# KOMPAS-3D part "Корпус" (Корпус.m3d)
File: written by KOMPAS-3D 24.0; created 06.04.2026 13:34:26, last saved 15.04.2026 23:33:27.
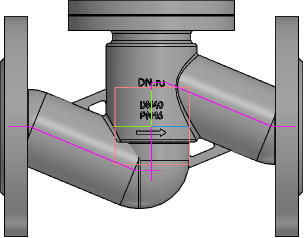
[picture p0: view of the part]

Document properties: Автор: R2D2; Полное имя файла: E:\Работа\Зайцев\VSO3131M-F-S Клапан запорный DN.ru Ду15-100 Ру16\DN40\исходные материалы\Корпус.m3d

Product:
- Body: Труба / Нестандартная труба / L = 100.7 мм  | qty 1
    Материал: Нестандартная труба (density 7856 kg/m3)
    Масса: 9.117436
    Раздел спецификации: Детали
    Примечание: 1,55 кг
    additional columns: Pipeline; 0.05; 0; 0; 0.002; 0.1007; true; 0.04
- Body: Труба / Нестандартная труба / L = 126.7 мм  | qty 1
    Материал: Нестандартная труба (density 7856 kg/m3)
    Масса: 9.117436
    Раздел спецификации: Детали
    Примечание: 1,95 кг
    additional columns: Pipeline; 0.05; 0; 0; 0.002; 0.12669; true; 0.04
- Body: Тело 4  | qty 1
    Материал: Нестандартная труба (density 7856 kg/m3)
    Масса: 9.117436
- Body: Тело 5  | qty 1
    Материал: Нестандартная труба (density 7856 kg/m3)
    Масса: 9.117436
- Body: Тело 8  | qty 1
    Материал: Нестандартная труба (density 7856 kg/m3)
    Масса: 9.117436
- Body: Тело 9  | qty 1
    Материал: Нестандартная труба (density 7856 kg/m3)
    Масса: 9.117436
- Part/product: Корпус
    Масса: 6.9

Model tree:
1. Труба
2. Труба:1  (labels: {F703FF30-5BE6-4673-A7F1-8EDA1BE1E2D1}; SHAPEOBJECT3D_ATTR_BUTT; SHAPEOBJECT3D_ATTR_VALID; SHAPEOBJECT3D_ATTR_BUTT_AREA)
     PIPE_R = 7
3. Труба:2  (labels: {F703FF30-5BE6-4673-A7F1-8EDA1BE1E2D1}; SHAPEOBJECT3D_ATTR_BUTT; SHAPEOBJECT3D_ATTR_VALID; SHAPEOBJECT3D_ATTR_BUTT_AREA)
     PIPE_R = 7
4. Колонна
5. Элемент выдавливания:1
     Смещение 1 = -1; Расстояние 2 = 3.29028e-05; Смещение 2 = -5
6. Скругление:17  (with: Ребро.Элемент выдавливания:1)
     Радиус = 1
7. Скругление:18  (with: Ребро.Элемент выдавливания:1)
8. Скругление:24  (with: Ребро.Элемент выдавливания:1)
     Радиус = 1.5
9. Элемент выдавливания:2
     Расстояние 1 = 6
10. Скругление:19  (with: Ребро.Элемент выдавливания:2)
     Радиус = 2
11. Эскиз:4  (with: Грань.Элемент выдавливания:1)
12. Элемент выдавливания:3
     Расстояние 1 = 8.5; Смещение 1 = 141322
13. Скругление:21  (with: Ребро.Элемент выдавливания:3)
14. ОТЛИВКА
15. Скругление:6  (with: Грань.Элемент выдавливания:1)
     Радиус = 2
16. Элемент выдавливания:6  (with: Грань.Элемент выдавливания:1)
     Смещение 1 = 4
17. ЛЕЙБЛ
18. Элемент выдавливания:7  (with: Грань.Элемент выдавливания:1)
     Расстояние 1 = 30.9952; Смещение 1 = 1
19. Фланец верх  (with: Ребро.Элемент выдавливания:3)
20. Элемент вращения:2
     Угол 1 = 360
21. Эскиз:12  (with: Грань.Элемент вращения:2)
22. Элемент выдавливания:9  (with: Грань.Элемент вращения:2)
     Расстояние 2 = 20
23. Массив по концентрической сетке:1  (with: Элемент выдавливания:9, Эскиз:12, Грань.Элемент вращения:2)  (4 pattern instances)
     Шаг 2 = 360
24. Фланец
25. Элемент вращения:1
     Угол 1 = 360
26. отвертие во фланце  (with: Грань.Элемент вращения:1)
27. Элемент выдавливания:8
28. Массив по концентрической сетке:2  (with: Элемент выдавливания:8, Эскиз:10, Грань.Элемент вращения:1)  (4 pattern instances)
     Шаг 2 = 360
29. Зеркальный массив:1
30. Экземпляр ( 1 )
31. Экземпляр ( 2 )  (with: Элемент вращения:1, Массив по концентрической сетке:2, Экземпляр ( 1 ), Элемент выдавливания:8)
32. Экземпляр ( 3 )  (with: Элемент выдавливания:8)
33. Экземпляр ( 4 )  (with: Элемент выдавливания:8)
34. Скругление:25  (with: Ребро.Элемент вращения:2)
     Радиус = 2

Expressions: DS/2+3; D1/2; DN/2; DS-v977*4; LL/2; D1-v1234*2; D/2-9
Referenced files in C:\Program Files\ASCON\KOMPAS-3D v24\Libs\Pipeline\: StylesTemplate.a3d, TemplateHPH, InsulationStylesTemplate.a3d, Insulation
Referenced files in C:\Program Files\ASCON\KOMPAS-3D v24\Templates\: Констр. чертеж А3 гориз. перв. лист.cdt
Referenced files in E:\Работа\Зайцев\VSO3131M-F-S Клапан запорный DN.ru Ду15-100 Ру40\DN20\исходные материалы\: 
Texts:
  Отводы ГОСТ 17375-2001
  Констр. чертеж А3 гориз. перв. лист.cdt
  GOST 26.020 Pr3
  var3D
  GOST 2.304 type A
  смещение колонны вниз
  LL-10
  DN+10
  Труба / Нестандартная труба / L = %s мм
